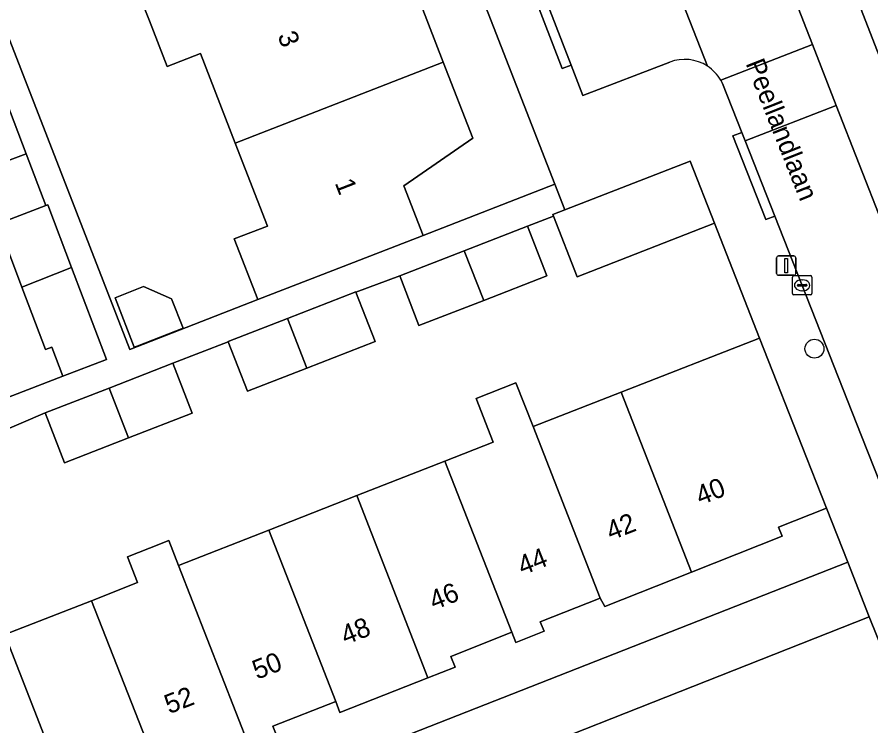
# Model space of a CAD drawing. Extents: x 159680 to 160786, y 387323 to 388340.
# Drawn here: x 159993.17 to 160037.27, y 387669.11 to 387705.71 of the extents above; entities that cross this region are included whole.
import ezdxf

# ---------------------------------------------------------------- set-up
doc = ezdxf.new("R2010")
doc.units = 0
for name, color, linetype in [('IMGEO_Boom', 7, 'Continuous'), ('IMGEO_Erf', 7, 'Continuous'), ('IMGEO_Groenvoorziening', 7, 'Continuous'), ('IMGEO_Kolk', 7, 'Continuous'), ('IMGEO_Lichtmast', 7, 'Continuous'), ('IMGEO_Muur', 7, 'Continuous'), ('IMGEO_Openbare_ruimte_label', 7, 'Continuous'), ('IMGEO_Pand', 7, 'Continuous'), ('IMGEO_Pand_nummerreeks', 7, 'Continuous'), ('IMGEO_Parkeervlak_open', 7, 'Continuous'), ('IMGEO_Rijbaan_lokaal_open', 7, 'Continuous'), ('IMGEO_Voetpad_open', 7, 'Continuous')]:
    doc.layers.add(name, color=color, linetype=linetype)

msp = doc.modelspace()

# ---------------------------------------------------------------- linework, layer by layer
at = {"layer": 'IMGEO_Boom'}
msp.add_circle((160034.347, 387688.587), 0.489, dxfattribs=at)
at = {"layer": 'IMGEO_Erf'}
for points in [[(159995.682, 387741.712), (159996.618, 387739.305), (159997.553, 387736.899), (160000, 387737.032), (160001.989, 387737.141), (160003.523, 387733.195), (160005.056, 387729.25), (160001.515, 387726.886), (160002.466, 387724.44), (160003.416, 387721.997), (160007.807, 387722.232), (160009.336, 387718.298), (160010.865, 387714.366), (160007.272, 387712.031), (160008.244, 387709.529), (160009.217, 387707.026), (160013.649, 387707.319), (160015.175, 387703.392), (160016.701, 387699.467), (160013.143, 387696.999), (160014.138, 387694.441), (160020.94, 387697.092), (160000.318, 387750)], [(159975.76, 387748.314), (159998.986, 387688.539), (160005.599, 387691.121), (160004.381, 387694.254), (160006.104, 387694.923), (160004.437, 387699.21), (160002.643, 387703.826), (160000.921, 387703.156), (160000, 387705.525), (159999.732, 387706.214), (160001.454, 387706.885), (159998.637, 387714.132), (159998.573, 387714.296), (159995.401, 387713.06), (159993.584, 387717.732), (159995.036, 387718.296), (159993.938, 387721.12), (159992.779, 387724.102), (159994.501, 387724.772), (159992.842, 387729.037)], [(160024.811, 387736.808), (160043.442, 387688.944)], [(159985.628, 387683.346), (159995.528, 387687.167), (159994.961, 387688.661), (159994.638, 387688.538), (159993.41, 387691.772), (159992.168, 387695.043), (159994.644, 387695.982), (159993.628, 387698.659), (159991.048, 387697.679)], [(159992.531, 387673.821), (159997.017, 387675.574), (159999.386, 387676.51), (159998.865, 387677.843), (160000, 387678.287), (160000.999, 387678.677), (160001.499, 387677.398), (160006.161, 387679.222), (160010.711, 387681.002), (160015.262, 387682.782), (160017.752, 387683.756), (160016.869, 387686.017), (160018.931, 387686.823), (160019.814, 387684.563), (160024.366, 387686.343), (160031.513, 387689.139), (160029.18, 387695.062), (160022.085, 387692.306), (160020.869, 387695.436), (160019.524, 387694.913), (160020.523, 387692.343), (160017.268, 387691.078), (160013.924, 387689.779), (160012.926, 387692.349), (160010.665, 387691.508), (160011.658, 387688.954), (160008.138, 387687.586), (160005.06, 387686.39), (160004.068, 387688.943), (160001.215, 387687.834), (160002.214, 387685.264), (159998.923, 387683.985), (159995.616, 387682.7), (159994.617, 387685.27), (159992.115, 387684.207)], [(160036.074, 387677.556), (160034.971, 387680.356), (160032.493, 387679.375), (160032.676, 387678.913), (160027.996, 387677.051), (160023.515, 387675.268), (160023.275, 387675.706), (160020.19, 387674.486), (160020.385, 387673.992), (160018.928, 387673.415), (160018.717, 387673.949), (160015.572, 387672.693), (160015.791, 387672.146), (160014.388, 387671.594), (160009.84, 387669.805), (160009.622, 387670.364), (160006.381, 387669.097), (160006.621, 387668.483), (160005.202, 387667.928), (160000.692, 387666.166), (160000, 387665.896), (159996.207, 387664.414), (159991.655, 387662.635)], [(159982.18, 387656.4), (160000, 387663.396), (160036.074, 387677.556)]]:
    msp.add_lwpolyline(points, dxfattribs=at)
msp.add_lwpolyline([(160001.15, 387691.159), (160001.737, 387689.64), (159999.376, 387688.723), (159999.217, 387688.661), (159998.224, 387691.217), (159999.702, 387691.791)], close=True, dxfattribs=at)
at = {"layer": 'IMGEO_Groenvoorziening'}
msp.add_lwpolyline([(160039.479, 387669.024), (160037.17, 387674.748), (160009.204, 387663.69), (160010.995, 387658.901), (160034.981, 387668.279)], dxfattribs=at)
at = {"layer": 'IMGEO_Kolk'}
for p, q in [((160033.211, 387691.435), (160033.211, 387692.287)), ((160033.286, 387692.361), (160034.138, 387692.361)), ((160033.699, 387692.141), (160033.724, 387692.141)), ((160034.212, 387692.287), (160034.212, 387691.435)), ((160033.47, 387691.855), (160033.47, 387691.867)), ((160033.908, 387691.818), (160033.51, 387691.818)), ((160033.513, 387691.904), (160033.911, 387691.904)), ((160033.722, 387691.581), (160033.697, 387691.581)), ((160033.954, 387691.867), (160033.954, 387691.855)), ((160034.138, 387691.361), (160033.286, 387691.361))]:
    msp.add_line(p, q, dxfattribs=at)
for points in [[(160033.211, 387691.435), (160033.211, 387692.287)], [(160033.286, 387692.361), (160034.138, 387692.361)], [(160034.212, 387692.287), (160034.212, 387691.435)], [(160034.138, 387691.361), (160033.286, 387691.361)]]:
    msp.add_lwpolyline(points, dxfattribs=at)
for centre, radius, start, end in [((160033.288, 387692.285), 0.0765, 91.552, 178.448), ((160033.288, 387692.285), 0.0765, 91.552, 178.448), ((160034.136, 387692.285), 0.0765, 1.552, 88.448), ((160034.136, 387692.285), 0.0765, 1.552, 88.448), ((160033.51, 387691.864), 0.0403, 85.8775, 175.7526), ((160033.507, 387691.854), 0.0366, 178.938, 274.7102), ((160033.911, 387691.861), 0.043, 264.8664, 352.4533), ((160033.915, 387691.866), 0.0386, 1.7309, 96.639), ((160033.288, 387691.437), 0.0765, 181.552, 268.448), ((160033.288, 387691.437), 0.0765, 181.552, 268.448), ((160034.136, 387691.437), 0.0765, 271.552, 358.448), ((160034.136, 387691.437), 0.0765, 271.552, 358.448)]:
    msp.add_arc(centre, radius, start, end, dxfattribs=at)
for centre, major_axis, ratio, start_param, end_param in [((160033.698, 387691.861), (-0.387, 0.002), 0.722429, 4.712389, 7.853982), ((160033.723, 387691.861), (-0.39, 0.002), 0.717154, 1.570796, 4.712389)]:
    msp.add_ellipse(centre, major_axis=major_axis, ratio=ratio, start_param=start_param, end_param=end_param, dxfattribs=at)
at = {"layer": 'IMGEO_Lichtmast'}
for p, q in [((160032.491, 387693.377), (160033.281, 387693.377)), ((160033.281, 387693.377), (160032.491, 387693.377)), ((160032.391, 387692.477), (160032.391, 387693.277)), ((160032.391, 387693.277), (160032.391, 387692.477)), ((160033.381, 387693.277), (160033.381, 387692.477)), ((160033.381, 387692.477), (160033.381, 387693.277)), ((160033.281, 387692.377), (160032.491, 387692.377)), ((160032.491, 387692.377), (160033.281, 387692.377))]:
    msp.add_line(p, q, dxfattribs=at)
msp.add_lwpolyline([(160032.811, 387693.252), (160032.961, 387693.252), (160032.961, 387692.502), (160032.811, 387692.502), (160032.811, 387693.252)], dxfattribs=at)
for centre, start, end in [((160032.491, 387693.277), 90, 180), ((160032.491, 387693.277), 90, 180), ((160033.281, 387693.277), 0, 90), ((160033.281, 387693.277), 360, 90), ((160032.491, 387692.477), 180, 270), ((160032.491, 387692.477), 180, 270), ((160033.281, 387692.477), 270, 0), ((160033.281, 387692.477), 270, 0)]:
    msp.add_arc(centre, 0.1, start, end, dxfattribs=at)
at = {"layer": 'IMGEO_Muur'}
msp.add_lwpolyline([(160029.18, 387695.062), (160031.513, 387689.139)], dxfattribs=at)
at = {"layer": 'IMGEO_Pand'}
for points in [[(160008.244, 387709.529), (160001.454, 387706.885), (159999.732, 387706.214), (160000, 387705.525), (160000.921, 387703.156), (160002.643, 387703.826), (160004.437, 387699.21), (160015.175, 387703.392), (160013.649, 387707.319), (160009.217, 387707.026)], [(160015.175, 387703.392), (160004.437, 387699.21), (160006.104, 387694.923), (160004.381, 387694.254), (160005.599, 387691.121), (160009.478, 387692.629), (160014.138, 387694.441), (160013.143, 387696.999), (160016.701, 387699.467)], [(159991.048, 387697.679), (159993.628, 387698.659), (159992.391, 387701.915), (159989.82, 387700.914)], [(160027.934, 387698.27), (160021.461, 387695.756), (160020.839, 387695.514), (160020.869, 387695.436), (160022.085, 387692.306), (160029.18, 387695.062)], [(159994.748, 387696.022), (159994.644, 387695.982), (159992.168, 387695.043), (159993.41, 387691.772), (159995.982, 387692.773)], [(160016.265, 387693.646), (160017.268, 387691.078), (160020.523, 387692.343), (160019.524, 387694.913)], [(160017.268, 387691.078), (160016.265, 387693.646), (160012.926, 387692.349), (160013.924, 387689.779)], [(159995.982, 387692.773), (159993.41, 387691.772), (159994.638, 387688.538), (159994.961, 387688.661), (159995.528, 387687.167), (159997.785, 387688.024)], [(160001.737, 387689.64), (160001.15, 387691.159), (159999.702, 387691.791), (159998.224, 387691.217), (159999.217, 387688.661), (159999.376, 387688.723)], [(160010.665, 387691.508), (160010.659, 387691.524), (160007.134, 387690.154), (160008.138, 387687.586), (160011.658, 387688.954)], [(160007.134, 387690.154), (160004.061, 387688.96), (160004.068, 387688.943), (160005.06, 387686.39), (160008.138, 387687.586)], [(160033.94, 387682.976), (160031.513, 387689.139), (160024.366, 387686.343), (160027.996, 387677.051), (160032.676, 387678.913), (160032.493, 387679.375), (160034.971, 387680.356)], [(159997.919, 387686.553), (159998.923, 387683.985), (160002.214, 387685.264), (160001.215, 387687.834)], [(160015.262, 387682.782), (160018.717, 387673.949), (160018.928, 387673.415), (160020.385, 387673.992), (160020.19, 387674.486), (160023.275, 387675.706), (160019.814, 387684.563), (160018.931, 387686.823), (160016.869, 387686.017), (160017.752, 387683.756)], [(159998.923, 387683.985), (159997.919, 387686.553), (159994.617, 387685.27), (159995.616, 387682.7)], [(160023.275, 387675.706), (160023.515, 387675.268), (160027.996, 387677.051), (160024.366, 387686.343), (160019.814, 387684.563)], [(160014.388, 387671.594), (160015.791, 387672.146), (160015.572, 387672.693), (160018.717, 387673.949), (160015.262, 387682.782), (160010.711, 387681.002)], [(160010.711, 387681.002), (160006.161, 387679.222), (160009.622, 387670.364), (160009.84, 387669.805), (160014.388, 387671.594)], [(160006.161, 387679.222), (160001.499, 387677.398), (160005.202, 387667.928), (160006.621, 387668.483), (160006.381, 387669.097), (160009.622, 387670.364)], [(160001.499, 387677.398), (160000.999, 387678.677), (160000, 387678.287), (159998.865, 387677.843), (159999.386, 387676.51), (159997.017, 387675.574), (160000, 387667.936), (160000.692, 387666.166), (160005.202, 387667.928)], [(159992.531, 387673.821), (159991.634, 387676.113), (159987.083, 387674.335), (159987.979, 387672.042), (159991.427, 387663.219), (159991.655, 387662.635), (159996.207, 387664.414)], [(159997.017, 387675.574), (159992.531, 387673.821), (159996.207, 387664.414), (160000, 387665.896), (160000.692, 387666.166), (160000, 387667.936)]]:
    msp.add_lwpolyline(points, close=True, dxfattribs=at)
at = {"layer": 'IMGEO_Parkeervlak_open'}
for points in [[(160028.819, 387703.181), (160016.916, 387733.521)], [(160015.59, 387732.032), (160011.193, 387730.259), (160013.761, 387723.511), (160016.218, 387717.369), (160019.367, 387709.498), (160020.568, 387706.378), (160021.776, 387703.229), (160022.38, 387701.656), (160026.873, 387703.385)]]:
    msp.add_lwpolyline(points, dxfattribs=at)
msp.add_arc((160027.646, 387701.376), 2.153, 56.9862, 111.0449, dxfattribs=at)
at = {"layer": 'IMGEO_Rijbaan_lokaal_open'}
for points in [[(160029.51, 387702.449), (160034.24, 387704.299), (160021.961, 387735.751)], [(160016.916, 387733.521), (160028.819, 387703.181)], [(160046.561, 387672.828), (160041.583, 387685.544), (160041.4, 387686.011), (160040.216, 387689.036), (160035.472, 387701.152), (160030.768, 387699.317), (160032.302, 387695.434), (160036.769, 387684.127), (160041.702, 387671.64)]]:
    msp.add_lwpolyline(points, dxfattribs=at)
msp.add_lwpolyline([(160034.24, 387704.299), (160029.51, 387702.449), (160029.598, 387702.278), (160030.593, 387699.761), (160030.768, 387699.317), (160035.472, 387701.152)], close=True, dxfattribs=at)
msp.add_arc((160027.645, 387701.381), 2.149, 29.8035, 56.8957, dxfattribs=at)
at = {"layer": 'IMGEO_Voetpad_open'}
for points in [[(160000.318, 387750), (160020.94, 387697.092), (160021.461, 387695.756), (160027.934, 387698.27), (160029.18, 387695.062), (160031.513, 387689.139), (160033.94, 387682.976), (160034.971, 387680.356), (160036.074, 387677.556), (160037.17, 387674.748), (160039.479, 387669.024)], [(159992.115, 387684.207), (159994.617, 387685.27), (159997.919, 387686.553), (160001.215, 387687.834), (160004.068, 387688.943), (160004.061, 387688.96), (160007.134, 387690.154), (160010.659, 387691.524), (160010.665, 387691.508), (160012.926, 387692.349), (160016.265, 387693.646), (160019.524, 387694.913), (160020.869, 387695.436), (160020.839, 387695.514), (160021.461, 387695.756), (160020.94, 387697.092), (160014.138, 387694.441), (160009.478, 387692.629), (160005.599, 387691.121), (159998.986, 387688.539), (159975.76, 387748.314)], [(160043.442, 387688.944), (160024.811, 387736.808), (160022.437, 387741.08)], [(160021.961, 387735.751), (160034.24, 387704.299), (160035.472, 387701.152), (160040.216, 387689.036), (160041.193, 387689.419), (160042.373, 387686.406), (160042.561, 387685.927), (160041.583, 387685.544), (160046.561, 387672.828)], [(160026.873, 387703.385), (160022.38, 387701.656), (160021.776, 387703.229), (160021.31, 387703.052), (160018.9, 387709.321), (160019.367, 387709.498), (160016.218, 387717.369), (160015.484, 387717.085), (160013.094, 387723.253), (160013.761, 387723.511), (160011.193, 387730.259), (160015.59, 387732.032)], [(160030.128, 387699.58), (160030.593, 387699.761), (160029.598, 387702.278), (160029.51, 387702.449)], [(159992.391, 387701.915), (159993.628, 387698.659), (159994.644, 387695.982), (159994.748, 387696.022), (159995.982, 387692.773), (159997.785, 387688.024), (159995.528, 387687.167), (159985.628, 387683.346)], [(160041.702, 387671.64), (160036.769, 387684.127), (160032.302, 387695.434), (160031.837, 387695.253), (160030.128, 387699.58)], [(160010.995, 387658.901), (160009.204, 387663.69), (160037.17, 387674.748), (160036.074, 387677.556), (160000, 387663.396), (159982.18, 387656.4)]]:
    msp.add_lwpolyline(points, dxfattribs=at)
for points in [[(160019.367, 387709.498), (160018.9, 387709.321), (160021.31, 387703.052), (160021.776, 387703.229), (160020.568, 387706.378)], [(160030.768, 387699.317), (160030.593, 387699.761), (160030.128, 387699.58), (160031.837, 387695.253), (160032.302, 387695.434)]]:
    msp.add_lwpolyline(points, close=True, dxfattribs=at)
for centre, radius, start, end in [((160027.646, 387701.376), 2.153, 56.9862, 111.0449), ((160027.645, 387701.381), 2.149, 29.8035, 56.8957)]:
    msp.add_arc(centre, radius, start, end, dxfattribs=at)

# ---------------------------------------------------------------- texts
at = {"layer": 'IMGEO_Openbare_ruimte_label'}
msp.add_text('Peellandlaan', height=1, rotation=291.663, dxfattribs=at).set_placement((160030.779, 387703.322))
at = {"layer": 'IMGEO_Pand_nummerreeks'}
for s, rotation, p in [('3', 291.2623, (160006.604, 387704.757)), ('1', 291.2623, (160009.563, 387697.151)), ('40', 21.5978, (160028.459, 387680.488)), ('42', 21.454, (160023.834, 387678.666)), ('44', 21.454, (160019.267, 387676.871)), ('46', 21.454, (160014.696, 387675.075)), ('48', 21.4515, (160010.129, 387673.28)), ('50', 21.4515, (160005.559, 387671.484)), ('52', 21.3541, (160001.017, 387669.706))]:
    msp.add_text(s, height=1, rotation=rotation, dxfattribs=at).set_placement(p)

doc.saveas('drawing.dxf')
